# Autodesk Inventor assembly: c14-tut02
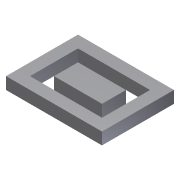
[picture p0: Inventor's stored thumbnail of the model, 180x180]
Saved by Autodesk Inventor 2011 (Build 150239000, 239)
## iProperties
Created: 2010-04
Part Number: c14-tut02
Document SubType Name: Assembly
Designer: CADSoft
Author: CADSoft
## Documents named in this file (3)
- C:\Users\CADSoft\Desktop\part files\c14-inv-2011-prt\c14-tut02-inv\c14-tut02.iam
- C:\Inventor_2011\tutorials\Outer Plate.ipt
- C:\Inventor_2011\tutorials\Inner Plate.ipt
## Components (2 placed, 2 different names)
1. Outer Plate:1 — Flush:1, Flush:2, Mate:1, Mate:2, Mate:3, Mate:4
2. Inner Plate:1 — Flush:1, Flush:2, Mate:1, Mate:2, Mate:3, Mate:4
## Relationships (6: Mate 4, Flush 2)
- Flush:1: Outer Plate:1 ↔ Inner Plate:1
- Flush:2: Outer Plate:1 ↔ Inner Plate:1
- Mate:1: Outer Plate:1 ↔ Inner Plate:1
- Mate:2: Outer Plate:1 ↔ Inner Plate:1
- Mate:3: Outer Plate:1 ↔ Inner Plate:1
- Mate:4: Outer Plate:1 ↔ Inner Plate:1
